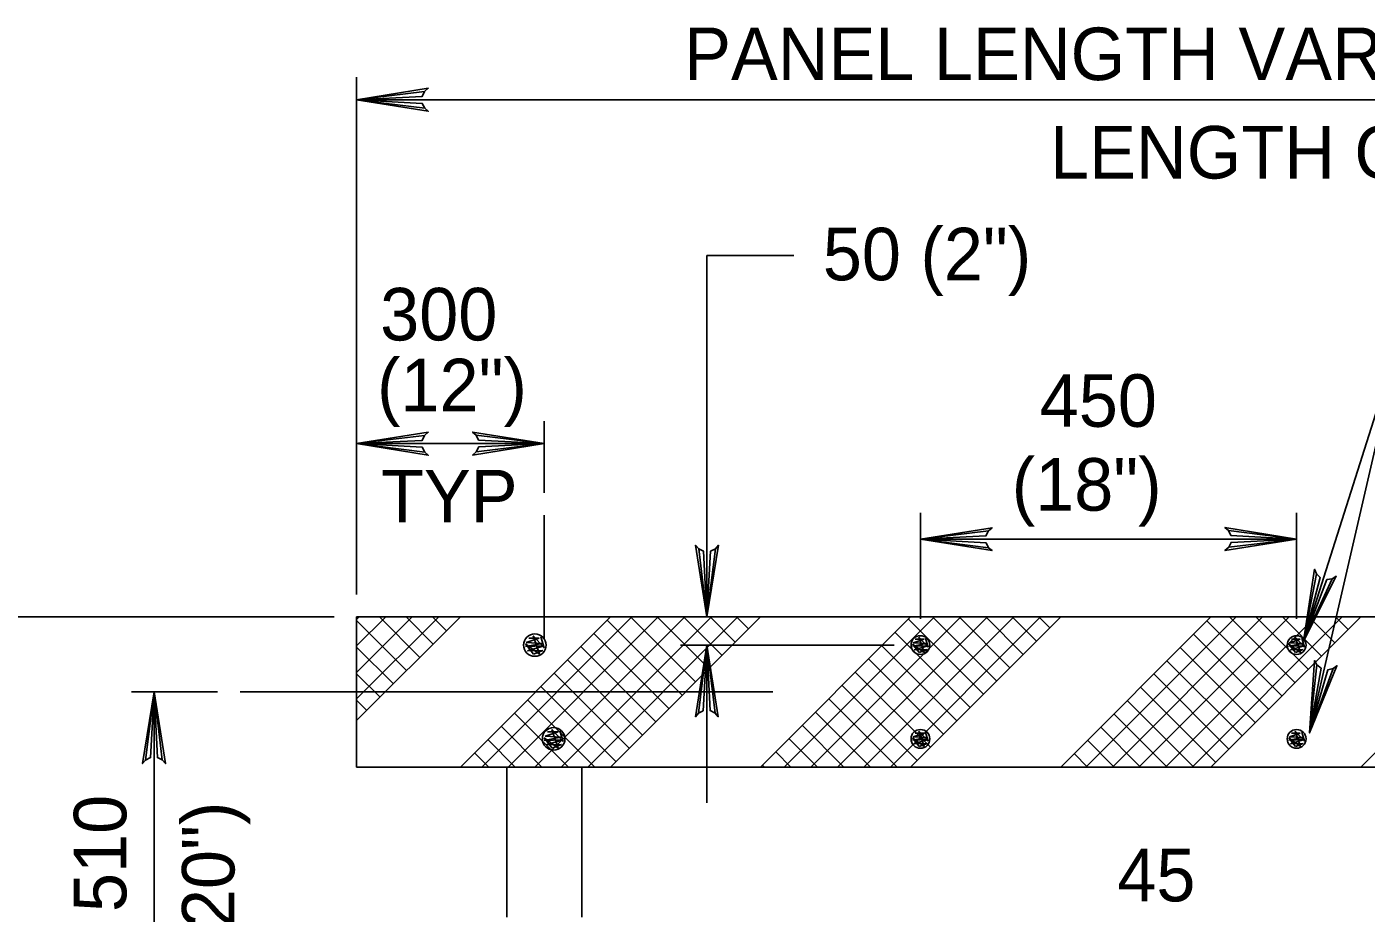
# Model space of a CAD drawing. Extents: x -4 to 901, y -468 to 720.
# Drawn here: x 89.7 to 175.4, y -279.2 to -222.5 of the extents above; entities that cross this region are included whole.
import ezdxf

# ---------------------------------------------------------------- set-up
doc = ezdxf.new("R2010")
doc.units = 0
doc.layers.add('2', color=7, linetype='Continuous')
doc.layers.add('3', color=7, linetype='Continuous')

msp = doc.modelspace()

# ---------------------------------------------------------------- linework, layer by layer
at = {"layer": '2'}
for p, q in [((110.77575, -258.767625), (110.77575, -225.697625)), ((254.77575, -227.137625), (110.77575, -227.137625)), ((133.17975, -260.207625), (133.17975, -237.102625)), ((122.77575, -252.269625), (122.77575, -247.689625)), ((122.77575, -249.129625), (110.77575, -249.129625)), ((146.83775, -260.327625), (146.83775, -253.553625)), ((170.90175, -260.327625), (170.90175, -253.553625)), ((122.77575, -261.589625), (122.77575, -253.709625)), ((146.83775, -255.233625), (170.90175, -255.233625)), ((109.33575, -260.207625), (65.93175, -260.207625)), ((110.77575, -266.841625), (117.40975, -260.207625)), ((110.77575, -260.207625), (254.77575, -260.207625)), ((110.77575, -260.207625), (254.77575, -260.207625)), ((110.77575, -269.807625), (110.77575, -260.207625)), ((110.77575, -260.207625), (254.77575, -260.207625)), ((112.45575, -260.207625), (134.85975, -260.207625)), ((117.40975, -269.807625), (127.00975, -260.207625)), ((127.00975, -269.807625), (136.60975, -260.207625)), ((136.60975, -269.807625), (146.20975, -260.207625)), ((146.20975, -269.807625), (155.80975, -260.207625)), ((155.80975, -269.807625), (165.40975, -260.207625)), ((165.40975, -269.807625), (175.00975, -260.207625)), ((175.00975, -269.807625), (184.60975, -260.207625)), ((122.64375, -261.899625), (121.57775, -262.101625)), ((122.08975, -262.591625), (121.57775, -261.935625)), ((121.57775, -261.935625), (122.47175, -262.591625)), ((121.57775, -262.101625), (122.76575, -262.059625)), ((122.45575, -261.561625), (121.62775, -261.843625)), ((121.62775, -261.843625), (122.64375, -261.899625)), ((122.76575, -262.059625), (121.70775, -262.383625)), ((121.77975, -261.561625), (122.45575, -261.561625)), ((122.47175, -262.591625), (122.05975, -261.411625)), ((122.05975, -261.411625), (122.77975, -262.181625)), ((122.17575, -262.007625), (122.17575, -262.007625)), ((122.77975, -262.181625), (122.56375, -261.483625)), ((122.77575, -262.007625), (122.77575, -262.007625)), ((145.15775, -262.007625), (131.49975, -262.007625)), ((147.22775, -261.917625), (146.33975, -262.085625)), ((146.76575, -262.493625), (146.33975, -261.947625)), ((146.33975, -261.947625), (147.08375, -262.493625)), ((146.33975, -262.085625), (147.32975, -262.049625)), ((147.07175, -261.635625), (146.38175, -261.869625)), ((146.38175, -261.869625), (147.22775, -261.917625)), ((147.32975, -262.049625), (146.44775, -262.319625)), ((146.50775, -261.635625), (147.07175, -261.635625)), ((147.08375, -262.493625), (146.74175, -261.509625)), ((146.74175, -261.509625), (147.34175, -262.151625)), ((146.83775, -262.007625), (146.83775, -262.007625)), ((146.83775, -262.007625), (146.83775, -262.007625)), ((147.34175, -262.151625), (147.16175, -261.569625)), ((171.29175, -261.917625), (170.40375, -262.085625)), ((170.82975, -262.493625), (170.40375, -261.947625)), ((170.40375, -261.947625), (171.14775, -262.493625)), ((170.40375, -262.085625), (171.39375, -262.049625)), ((171.13575, -261.635625), (170.44575, -261.869625)), ((170.44575, -261.869625), (171.29175, -261.917625)), ((171.39375, -262.049625), (170.51175, -262.319625)), ((170.57175, -261.635625), (171.13575, -261.635625)), ((171.14775, -262.493625), (170.80575, -261.509625)), ((170.80575, -261.509625), (171.40575, -262.151625)), ((170.90175, -262.007625), (170.90175, -262.007625)), ((170.90175, -262.007625), (170.90175, -262.007625)), ((171.40575, -262.151625), (171.22575, -261.569625)), ((121.70775, -262.383625), (122.68775, -262.361625)), ((122.68775, -262.361625), (122.08975, -262.591625)), ((146.44775, -262.319625), (147.26375, -262.301625)), ((147.26375, -262.301625), (146.76575, -262.493625)), ((170.51175, -262.319625), (171.32775, -262.301625)), ((171.32775, -262.301625), (170.82975, -262.493625)), ((101.87775, -265.007625), (96.37975, -265.007625)), ((97.81975, -265.007625), (97.81975, -284.207625)), ((137.40575, -265.007625), (103.31775, -265.007625)), ((122.77575, -268.007625), (122.77575, -268.007625)), ((123.84375, -267.899625), (122.77775, -268.101625)), ((123.28975, -268.591625), (122.77775, -267.935625)), ((122.77775, -267.935625), (123.67175, -268.591625)), ((122.77775, -268.101625), (123.96575, -268.059625)), ((123.65575, -267.561625), (122.82775, -267.843625)), ((122.82775, -267.843625), (123.84375, -267.899625)), ((123.96575, -268.059625), (122.90775, -268.383625)), ((122.97975, -267.561625), (123.65575, -267.561625)), ((123.67175, -268.591625), (123.25975, -267.411625)), ((123.25975, -267.411625), (123.97975, -268.181625)), ((123.37575, -268.007625), (123.37575, -268.007625)), ((123.97975, -268.181625), (123.76375, -267.483625)), ((147.22775, -267.917625), (146.33975, -268.085625)), ((146.76575, -268.493625), (146.33975, -267.947625)), ((146.33975, -267.947625), (147.08375, -268.493625)), ((146.33975, -268.085625), (147.32975, -268.049625)), ((147.07175, -267.635625), (146.38175, -267.869625)), ((146.38175, -267.869625), (147.22775, -267.917625)), ((147.32975, -268.049625), (146.44775, -268.319625)), ((146.50775, -267.635625), (147.07175, -267.635625)), ((147.08375, -268.493625), (146.74175, -267.509625)), ((146.74175, -267.509625), (147.34175, -268.151625)), ((146.83775, -268.007625), (146.83775, -268.007625)), ((146.83775, -268.007625), (146.83775, -268.007625)), ((147.34175, -268.151625), (147.16175, -267.569625)), ((171.29175, -267.917625), (170.40375, -268.085625)), ((170.82975, -268.493625), (170.40375, -267.947625)), ((170.40375, -267.947625), (171.14775, -268.493625)), ((170.40375, -268.085625), (171.39375, -268.049625)), ((171.13575, -267.635625), (170.44575, -267.869625)), ((170.44575, -267.869625), (171.29175, -267.917625)), ((171.39375, -268.049625), (170.51175, -268.319625)), ((170.57175, -267.635625), (171.13575, -267.635625)), ((171.14775, -268.493625), (170.80575, -267.509625)), ((170.80575, -267.509625), (171.40575, -268.151625)), ((170.90175, -268.007625), (170.90175, -268.007625)), ((170.90175, -268.007625), (170.90175, -268.007625)), ((171.40575, -268.151625), (171.22575, -267.569625)), ((122.90775, -268.383625), (123.88775, -268.361625)), ((123.88775, -268.361625), (123.28975, -268.591625)), ((146.44775, -268.319625), (147.26375, -268.301625)), ((147.26375, -268.301625), (146.76575, -268.493625)), ((170.51175, -268.319625), (171.32775, -268.301625)), ((171.32775, -268.301625), (170.82975, -268.493625)), ((243.375, -269.807625), (110.77575, -269.807625))]:
    msp.add_line(p, q, dxfattribs=at)
for points in [[(115.13575, -227.685625), (114.97175, -227.369625), (110.77575, -227.137625), (115.13575, -227.685625), (115.35775, -227.875625), (110.77575, -227.137625), (114.96975, -226.929625), (115.12175, -226.617625), (110.77575, -227.137625), (115.35775, -226.409625), (115.12175, -226.617625)], [(133.17975, -237.102625), (138.7305, -237.102625)], [(178.43, -238.634125), (171.73175, -267.627625)], [(177.705, -241.772375), (171.33975, -261.751625)], [(115.13575, -249.675625), (114.97175, -249.359625), (110.77575, -249.129625), (115.13575, -249.675625), (115.35775, -249.867625), (110.77575, -249.129625), (114.96975, -248.921625), (115.12175, -248.609625), (110.77575, -249.129625), (115.35775, -248.399625), (115.12175, -248.609625)], [(118.41575, -248.581625), (118.57975, -248.897625), (122.77575, -249.129625), (118.41575, -248.581625), (118.19375, -248.389625), (122.77575, -249.129625), (118.58175, -249.335625), (118.42975, -249.647625), (122.77575, -249.129625), (118.19375, -249.857625), (118.42975, -249.647625)], [(151.19775, -255.781625), (151.03575, -255.465625), (146.83775, -255.233625), (151.19775, -255.781625), (151.42175, -255.971625), (146.83775, -255.233625), (151.03175, -255.025625), (151.18575, -254.713625), (146.83775, -255.233625), (151.42175, -254.505625), (151.18575, -254.713625)], [(166.54175, -254.685625), (166.70375, -255.001625), (170.90175, -255.233625), (166.54175, -254.685625), (166.31975, -254.495625), (170.90175, -255.233625), (166.70775, -255.441625), (166.55575, -255.753625), (170.90175, -255.233625), (166.31975, -255.961625), (166.55575, -255.753625)], [(133.72575, -255.849625), (133.41175, -256.011625), (133.17975, -260.207625), (133.72575, -255.849625), (133.91775, -255.625625), (133.17975, -260.207625), (132.97175, -256.015625), (132.65975, -255.861625), (133.17975, -260.207625), (132.45175, -255.625625), (132.65975, -255.861625)], [(173.18375, -257.763625), (172.83575, -257.823625), (171.33975, -261.751625), (173.18375, -257.763625), (173.43575, -257.609625), (171.33975, -261.751625), (172.41575, -257.693625), (172.16375, -257.451625), (171.33975, -261.751625), (172.03775, -257.163625), (172.16375, -257.451625)], [(110.77575, -265.457625), (116.02575, -260.207625)], [(110.77575, -263.761625), (114.32975, -260.207625)], [(110.77575, -262.063625), (112.63175, -260.207625)], [(110.77575, -260.367625), (110.93375, -260.207625)], [(113.97375, -263.643625), (110.77575, -260.445625)], [(114.82175, -262.795625), (112.23575, -260.207625)], [(115.67175, -261.947625), (113.93375, -260.209625)], [(116.51975, -261.097625), (115.62975, -260.207625)], [(117.36775, -260.249625), (117.32775, -260.207625)], [(118.77375, -269.807625), (128.37375, -260.209625)], [(120.47175, -269.807625), (130.07175, -260.207625)], [(122.16775, -269.807625), (131.76775, -260.207625)], [(123.86575, -269.807625), (133.46575, -260.207625)], [(125.56175, -269.807625), (135.16175, -260.207625)], [(131.60175, -265.215625), (126.80175, -260.415625)], [(132.45175, -264.365625), (128.29375, -260.207625)], [(133.29975, -263.517625), (129.98975, -260.207625)], [(134.14775, -262.669625), (131.68775, -260.207625)], [(134.99575, -261.821625), (133.38375, -260.207625)], [(135.84575, -260.971625), (135.08175, -260.207625)], [(138.12975, -269.807625), (147.72975, -260.207625)], [(139.82775, -269.807625), (149.42775, -260.207625)], [(141.52375, -269.807625), (151.12375, -260.207625)], [(143.22175, -269.807625), (152.82175, -260.207625)], [(144.91775, -269.807625), (154.51775, -260.207625)], [(150.86575, -265.151625), (146.06575, -260.351625)], [(151.71375, -264.303625), (147.61775, -260.207625)], [(152.56175, -263.455625), (149.31575, -260.207625)], [(153.41175, -262.607625), (151.01175, -260.207625)], [(154.25975, -261.757625), (152.70975, -260.207625)], [(155.10775, -260.909625), (154.40575, -260.207625)], [(157.42375, -269.807625), (167.02375, -260.207625)], [(159.12175, -269.807625), (168.71975, -260.207625)], [(160.81775, -269.807625), (170.41775, -260.207625)], [(162.51575, -269.807625), (172.11575, -260.207625)], [(164.21175, -269.807625), (173.81175, -260.207625)], [(170.80375, -264.413625), (166.59775, -260.207625)], [(171.65175, -263.565625), (168.29575, -260.207625)], [(172.49975, -262.717625), (169.99175, -260.209625)], [(173.34975, -261.867625), (171.68975, -260.207625)], [(174.19775, -261.019625), (173.38575, -260.207625)], [(130.75375, -266.063625), (125.95375, -261.263625)], [(150.01775, -266.001625), (145.21775, -261.201625)], [(169.10575, -266.111625), (164.30575, -261.311625)], [(169.95575, -265.263625), (165.15575, -260.463625)], [(113.12575, -264.491625), (110.77575, -262.141625)], [(129.90575, -266.911625), (125.10575, -262.111625)], [(132.63175, -266.367625), (132.94775, -266.205625), (133.17975, -262.007625), (132.63175, -266.367625), (132.44175, -266.591625), (133.17975, -262.007625), (133.38575, -266.201625), (133.69975, -266.355625), (133.17975, -262.007625), (133.90775, -266.591625), (133.69975, -266.355625)], [(133.17975, -262.007625), (133.17975, -272.087625)], [(149.16775, -266.849625), (144.36775, -262.049625)], [(168.25775, -266.959625), (163.45775, -262.159625)], [(129.05775, -267.761625), (124.25775, -262.961625)], [(148.31975, -267.697625), (143.51975, -262.897625)], [(167.40975, -267.807625), (162.60975, -263.007625)], [(173.24575, -263.503625), (172.90175, -263.591625), (171.73175, -267.627625), (173.24575, -263.503625), (173.48375, -263.329625), (171.73175, -267.627625), (172.47375, -263.495625), (172.20375, -263.275625), (171.73175, -267.627625), (172.05375, -262.999625), (172.20375, -263.275625)], [(112.27775, -265.341625), (110.77575, -263.839625)], [(128.20775, -268.609625), (123.40775, -263.809625)], [(147.47175, -268.547625), (142.67175, -263.747625)], [(166.56175, -268.657625), (161.76175, -263.857625)], [(127.35975, -269.457625), (122.55975, -264.657625)], [(146.62175, -269.395625), (141.82175, -264.595625)], [(165.71175, -269.505625), (160.91175, -264.705625)], [(97.27375, -269.367625), (97.58975, -269.205625), (97.81975, -265.007625), (97.27375, -269.367625), (97.08175, -269.591625), (97.81975, -265.007625), (98.02775, -269.201625), (98.33975, -269.355625), (97.81975, -265.007625), (98.54975, -269.591625), (98.33975, -269.355625)], [(111.42775, -266.189625), (110.77575, -265.535625)], [(126.01375, -269.807625), (121.71175, -265.505625)], [(145.33975, -269.807625), (140.97375, -265.443625)], [(164.31775, -269.807625), (160.06375, -265.553625)], [(124.31575, -269.807625), (120.86375, -266.355625)], [(143.64175, -269.807625), (140.12575, -266.291625)], [(162.62175, -269.807625), (159.21575, -266.401625)], [(122.61975, -269.807625), (120.01375, -267.203625)], [(141.94575, -269.807625), (139.27775, -267.141625)], [(160.92375, -269.807625), (158.36775, -267.251625)], [(120.92175, -269.807625), (119.16575, -268.051625)], [(140.24775, -269.807625), (138.42775, -267.989625)], [(159.22775, -269.807625), (157.51775, -268.099625)], [(119.22575, -269.807625), (118.31775, -268.899625)], [(138.55175, -269.807625), (137.57975, -268.837625)], [(157.52975, -269.807625), (156.66975, -268.947625)], [(117.52775, -269.807625), (117.46975, -269.749625)], [(120.37575, -279.407625), (120.37575, -269.807625), (125.17575, -269.807625), (125.17575, -279.407625)], [(136.85375, -269.807625), (136.73175, -269.685625)], [(155.83375, -269.807625), (155.82175, -269.795625)]]:
    msp.add_lwpolyline(points, dxfattribs=at)
for points in [[(110.77575, -266.841625), (110.77575, -260.207625), (117.40975, -260.207625)], [(117.40975, -269.807625), (127.00975, -260.207625), (136.60975, -260.207625), (127.00975, -269.807625)], [(136.60975, -269.807625), (146.20975, -260.207625), (155.80975, -260.207625), (146.20975, -269.807625)], [(155.80975, -269.807625), (165.40975, -260.207625), (175.00975, -260.207625), (165.40975, -269.807625)], [(175.00975, -269.807625), (184.60975, -260.207625), (194.20975, -260.207625), (184.60975, -269.807625)]]:
    msp.add_lwpolyline(points, close=True, dxfattribs=at)
for centre, radius in [((122.17589, -262.008528), 0.72), ((146.83853, -262.008528), 0.6), ((170.90141, -262.008528), 0.6), ((123.37589, -268.008528), 0.72), ((146.83853, -268.008528), 0.6), ((170.90141, -268.008528), 0.6)]:
    msp.add_circle(centre, radius, dxfattribs=at)

# ---------------------------------------------------------------- texts
at = {"layer": '3'}
for s, height, p in [('PANEL LENGTH VARIES WITH REQUIRED', 3.359988, (131.72175, -225.885625)), ('LENGTH OF BARRICADE', 3.359988, (155.13175, -232.177625)), ('50 (2")', 3.36, (140.594, -238.686125)), ('300', 3.36, (112.27825, -242.531125)), ('(12")', 3.36, (112.082, -247.061375)), ('450', 3.36, (154.46825, -248.053625)), ('(18")', 3.36, (152.68025, -253.416875)), ('TYP', 3.36, (112.33125, -254.169625)), ('45', 3.359988, (159.42975, -278.397625))]:
    msp.add_text(s, height=height, dxfattribs=at).set_placement(p)
for s, p in [('510', (96.0435, -279.081625)), ('(20")', (102.9595, -281.607625))]:
    msp.add_text(s, height=3.36, rotation=90, dxfattribs=at).set_placement(p)

doc.saveas('drawing.dxf')
